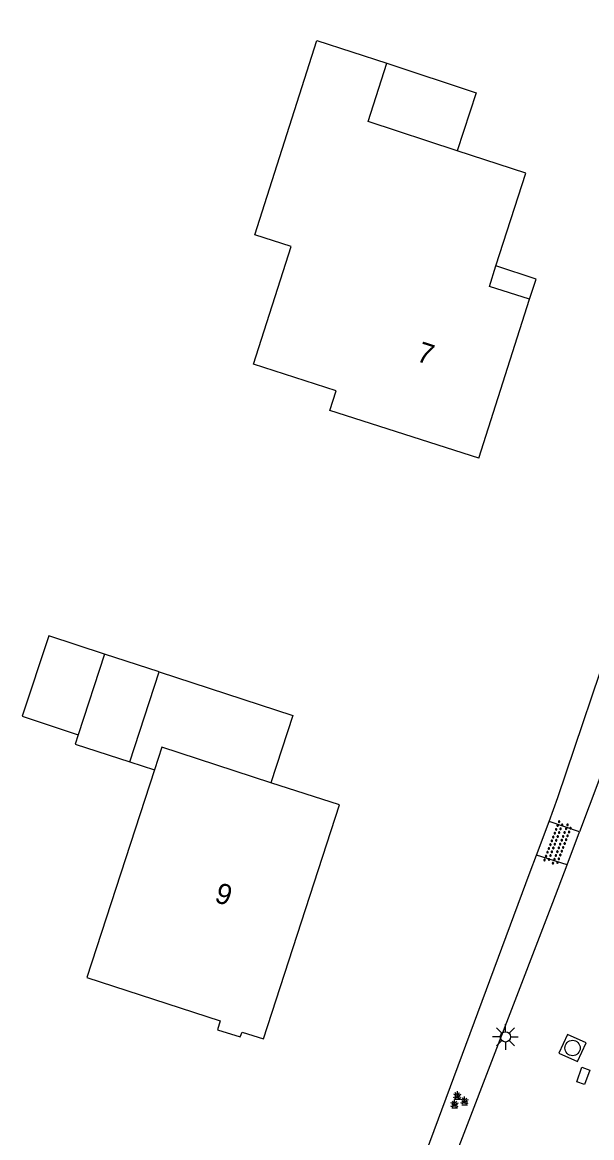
# Model space of a CAD drawing. Extents: x 128999 to 131010, y 395498 to 399007.
# Drawn here: x 130917.9 to 130945.7, y 396821 to 396875.4 of the extents above; entities that cross this region are included whole.
import ezdxf

# ---------------------------------------------------------------- set-up
doc = ezdxf.new("R2010")
doc.units = 0
for name, color, linetype in [('gg-afsc-erfafscheiding', 7, 'Continuous'), ('gg-anno-huisnummerreeks BGT', 7, 'Continuous'), ('gg-bbg-bijgebouw', 7, 'Continuous'), ('gg-bbg-gedigitaliseerde bebouwing', 7, 'Continuous'), ('gg-bbg-gedigitaliseerde bijgebouw', 7, 'Continuous'), ('gg-bbg-hoofdgebouw', 7, 'Continuous'), ('gg-bbg-luifel en loopbrug', 7, 'Continuous'), ('gg-knt-verharding', 7, 'Continuous'), ('gt-grn-groengrens', 7, 'Continuous'), ('gt-grn-weggrens', 7, 'Continuous'), ('gt-symb-groenvak', 7, 'Continuous'), ('gt-symb-kolk center center', 7, 'Continuous'), ('gt-symb-lichtmast', 7, 'Continuous'), ('gt-symb-overige verharding', 7, 'Continuous'), ('gt-symb-rioolschacht', 7, 'Continuous')]:
    doc.layers.add(name, color=color, linetype=linetype)

# ---------------------------------------------------------------- blocks, each defined once
blk = doc.blocks.new('gt0-KOLKCC')
at = {"layer": 'gt-symb-kolk center center'}
blk.add_lwpolyline([(-0.375, 0.2), (0.375, 0.2), (0.375, -0.2), (-0.375, -0.2)], close=True, dxfattribs=at)
blk = doc.blocks.new('gt0-GRVAK')
at = {"layer": 'gt-symb-groenvak'}
for p, q in [((-0.11, 0.189), (-0.228, 0.24)), ((-0.182, 0.153), (0.088, 0.153)), ((-0.091, 0.211), (-0.156, 0.322)), ((-0.047, 0.214), (-0.047, 0.393)), ((-0.004, 0.211), (0.061, 0.322)), ((0.015, 0.189), (0.133, 0.24)), ((0.262, -0.052), (0.197, 0.059)), ((0.305, -0.049), (0.305, 0.13)), ((0.349, -0.052), (0.414, 0.059)), ((-0.245, -0.228), (-0.363, -0.177)), ((-0.318, -0.264), (-0.047, -0.264)), ((-0.226, -0.206), (-0.291, -0.095)), ((-0.183, -0.203), (-0.183, -0.024)), ((-0.139, -0.206), (-0.074, -0.095)), ((-0.12, -0.228), (-0.002, -0.177)), ((0.243, -0.074), (0.125, -0.023)), ((0.17, -0.11), (0.441, -0.11)), ((0.368, -0.074), (0.486, -0.023))]:
    blk.add_line(p, q, dxfattribs=at)
blk = doc.blocks.new('gt0-LMAST')
at = {"layer": 'gt-symb-lichtmast'}
for p, q in [((-0.005, 0.246), (-0.005, 0.621)), ((-0.182, 0.173), (-0.447, 0.438)), ((0.172, 0.173), (0.437, 0.438)), ((-0.255, -0.004), (-0.63, -0.004)), ((-0.182, -0.181), (-0.447, -0.446)), ((-0.005, -0.254), (-0.005, -0.629)), ((0.437, -0.446), (0.172, -0.181)), ((0.245, -0.004), (0.62, -0.004))]:
    blk.add_line(p, q, dxfattribs=at)
blk.add_circle((-0.005, -0.004), 0.25, dxfattribs=at)
blk = doc.blocks.new('gt0-OVH')
at = {"layer": 'gt-symb-overige verharding'}
for points in [[(-0.972, 0.298), (-0.967, 0.308), (-0.965, 0.319), (-0.966, 0.33), (-0.971, 0.34), (-0.978, 0.348), (-0.988, 0.353), (-0.999, 0.355), (-1.01, 0.354), (-1.02, 0.349), (-1.028, 0.342), (-1.033, 0.332), (-1.035, 0.321), (-1.034, 0.31), (-1.029, 0.3), (-1.022, 0.292), (-1.012, 0.287), (-1.001, 0.285), (-0.99, 0.286), (-0.98, 0.291)], [(-0.872, 0.106), (-0.867, 0.116), (-0.865, 0.126), (-0.866, 0.137), (-0.871, 0.147), (-0.878, 0.156), (-0.888, 0.161), (-0.899, 0.163), (-0.91, 0.162), (-0.92, 0.157), (-0.928, 0.15), (-0.933, 0.14), (-0.935, 0.129), (-0.934, 0.118), (-0.929, 0.108), (-0.922, 0.1), (-0.912, 0.095), (-0.901, 0.092), (-0.89, 0.094), (-0.88, 0.098)], [(-0.772, 0.298), (-0.767, 0.308), (-0.765, 0.319), (-0.766, 0.33), (-0.771, 0.34), (-0.778, 0.348), (-0.788, 0.353), (-0.799, 0.355), (-0.81, 0.354), (-0.82, 0.349), (-0.828, 0.342), (-0.833, 0.332), (-0.835, 0.321), (-0.834, 0.31), (-0.829, 0.3), (-0.822, 0.292), (-0.812, 0.287), (-0.801, 0.285), (-0.79, 0.286), (-0.78, 0.291)], [(-0.672, 0.106), (-0.667, 0.116), (-0.665, 0.126), (-0.666, 0.137), (-0.671, 0.147), (-0.678, 0.156), (-0.688, 0.161), (-0.699, 0.163), (-0.71, 0.162), (-0.72, 0.157), (-0.728, 0.15), (-0.733, 0.14), (-0.735, 0.129), (-0.734, 0.118), (-0.729, 0.108), (-0.722, 0.1), (-0.712, 0.095), (-0.701, 0.092), (-0.69, 0.094), (-0.68, 0.098)], [(-0.572, 0.298), (-0.567, 0.308), (-0.565, 0.319), (-0.566, 0.33), (-0.571, 0.34), (-0.578, 0.348), (-0.588, 0.353), (-0.599, 0.355), (-0.61, 0.354), (-0.62, 0.349), (-0.628, 0.342), (-0.633, 0.332), (-0.635, 0.321), (-0.634, 0.31), (-0.629, 0.3), (-0.622, 0.292), (-0.612, 0.287), (-0.601, 0.285), (-0.59, 0.286), (-0.58, 0.291)], [(-0.472, 0.106), (-0.467, 0.116), (-0.465, 0.126), (-0.466, 0.137), (-0.471, 0.147), (-0.478, 0.156), (-0.488, 0.161), (-0.499, 0.163), (-0.51, 0.162), (-0.52, 0.157), (-0.528, 0.15), (-0.533, 0.14), (-0.535, 0.129), (-0.534, 0.118), (-0.529, 0.108), (-0.522, 0.1), (-0.512, 0.095), (-0.501, 0.092), (-0.49, 0.094), (-0.48, 0.098)], [(-0.372, 0.298), (-0.367, 0.308), (-0.365, 0.319), (-0.366, 0.33), (-0.371, 0.34), (-0.378, 0.348), (-0.388, 0.353), (-0.399, 0.355), (-0.41, 0.354), (-0.42, 0.349), (-0.428, 0.342), (-0.433, 0.332), (-0.435, 0.321), (-0.434, 0.31), (-0.429, 0.3), (-0.422, 0.292), (-0.412, 0.287), (-0.401, 0.285), (-0.39, 0.286), (-0.38, 0.291)], [(-0.272, 0.106), (-0.267, 0.116), (-0.265, 0.126), (-0.266, 0.137), (-0.271, 0.147), (-0.278, 0.156), (-0.288, 0.161), (-0.299, 0.163), (-0.31, 0.162), (-0.32, 0.157), (-0.328, 0.15), (-0.333, 0.14), (-0.335, 0.129), (-0.334, 0.118), (-0.329, 0.108), (-0.322, 0.1), (-0.312, 0.095), (-0.301, 0.092), (-0.29, 0.094), (-0.28, 0.098)], [(-0.172, 0.298), (-0.167, 0.308), (-0.165, 0.319), (-0.166, 0.33), (-0.171, 0.34), (-0.178, 0.348), (-0.188, 0.353), (-0.199, 0.355), (-0.21, 0.354), (-0.22, 0.349), (-0.228, 0.342), (-0.233, 0.332), (-0.235, 0.321), (-0.234, 0.31), (-0.229, 0.3), (-0.222, 0.292), (-0.212, 0.287), (-0.201, 0.285), (-0.19, 0.286), (-0.18, 0.291)], [(-0.072, 0.106), (-0.067, 0.116), (-0.065, 0.126), (-0.066, 0.137), (-0.071, 0.147), (-0.078, 0.156), (-0.088, 0.161), (-0.099, 0.163), (-0.11, 0.162), (-0.12, 0.157), (-0.128, 0.15), (-0.133, 0.14), (-0.135, 0.129), (-0.134, 0.118), (-0.129, 0.108), (-0.122, 0.1), (-0.112, 0.095), (-0.101, 0.092), (-0.09, 0.094), (-0.08, 0.098)], [(0.028, 0.298), (0.033, 0.308), (0.035, 0.319), (0.034, 0.33), (0.029, 0.34), (0.022, 0.348), (0.012, 0.353), (0.001, 0.355), (-0.01, 0.354), (-0.02, 0.349), (-0.028, 0.342), (-0.033, 0.332), (-0.035, 0.321), (-0.034, 0.31), (-0.029, 0.3), (-0.022, 0.292), (-0.012, 0.287), (-0.001, 0.285), (0.01, 0.286), (0.02, 0.291)], [(0.128, 0.106), (0.133, 0.116), (0.135, 0.126), (0.134, 0.137), (0.129, 0.147), (0.122, 0.156), (0.112, 0.161), (0.101, 0.163), (0.09, 0.162), (0.08, 0.157), (0.072, 0.15), (0.067, 0.14), (0.065, 0.129), (0.066, 0.118), (0.071, 0.108), (0.078, 0.1), (0.088, 0.095), (0.099, 0.092), (0.11, 0.094), (0.12, 0.098)], [(0.228, 0.298), (0.233, 0.308), (0.235, 0.319), (0.234, 0.33), (0.229, 0.34), (0.222, 0.348), (0.212, 0.353), (0.201, 0.355), (0.19, 0.354), (0.18, 0.349), (0.172, 0.342), (0.167, 0.332), (0.165, 0.321), (0.166, 0.31), (0.171, 0.3), (0.178, 0.292), (0.188, 0.287), (0.199, 0.285), (0.21, 0.286), (0.22, 0.291)], [(0.328, 0.106), (0.333, 0.116), (0.335, 0.126), (0.334, 0.137), (0.329, 0.147), (0.322, 0.156), (0.312, 0.161), (0.301, 0.163), (0.29, 0.162), (0.28, 0.157), (0.272, 0.15), (0.267, 0.14), (0.265, 0.129), (0.266, 0.118), (0.271, 0.108), (0.278, 0.1), (0.288, 0.095), (0.299, 0.092), (0.31, 0.094), (0.32, 0.098)], [(0.428, 0.298), (0.433, 0.308), (0.435, 0.319), (0.434, 0.33), (0.429, 0.34), (0.422, 0.348), (0.412, 0.353), (0.401, 0.355), (0.39, 0.354), (0.38, 0.349), (0.372, 0.342), (0.367, 0.332), (0.365, 0.321), (0.366, 0.31), (0.371, 0.3), (0.378, 0.292), (0.388, 0.287), (0.399, 0.285), (0.41, 0.286), (0.42, 0.291)], [(0.528, 0.106), (0.533, 0.116), (0.535, 0.126), (0.534, 0.137), (0.529, 0.147), (0.522, 0.156), (0.512, 0.161), (0.501, 0.163), (0.49, 0.162), (0.48, 0.157), (0.472, 0.15), (0.467, 0.14), (0.465, 0.129), (0.466, 0.118), (0.471, 0.108), (0.478, 0.1), (0.488, 0.095), (0.499, 0.092), (0.51, 0.094), (0.52, 0.098)], [(0.628, 0.298), (0.633, 0.308), (0.635, 0.319), (0.634, 0.33), (0.629, 0.34), (0.622, 0.348), (0.612, 0.353), (0.601, 0.355), (0.59, 0.354), (0.58, 0.349), (0.572, 0.342), (0.567, 0.332), (0.565, 0.321), (0.566, 0.31), (0.571, 0.3), (0.578, 0.292), (0.588, 0.287), (0.599, 0.285), (0.61, 0.286), (0.62, 0.291)], [(0.728, 0.106), (0.733, 0.116), (0.735, 0.126), (0.734, 0.137), (0.729, 0.147), (0.722, 0.156), (0.712, 0.161), (0.701, 0.163), (0.69, 0.162), (0.68, 0.157), (0.672, 0.15), (0.667, 0.14), (0.665, 0.129), (0.666, 0.118), (0.671, 0.108), (0.678, 0.1), (0.688, 0.095), (0.699, 0.092), (0.71, 0.094), (0.72, 0.098)], [(0.828, 0.298), (0.833, 0.308), (0.835, 0.319), (0.834, 0.33), (0.829, 0.34), (0.822, 0.348), (0.812, 0.353), (0.801, 0.355), (0.79, 0.354), (0.78, 0.349), (0.772, 0.342), (0.767, 0.332), (0.765, 0.321), (0.766, 0.31), (0.771, 0.3), (0.778, 0.292), (0.788, 0.287), (0.799, 0.285), (0.81, 0.286), (0.82, 0.291)], [(0.928, 0.106), (0.933, 0.116), (0.935, 0.126), (0.934, 0.137), (0.929, 0.147), (0.922, 0.156), (0.912, 0.161), (0.901, 0.163), (0.89, 0.162), (0.88, 0.157), (0.872, 0.15), (0.867, 0.14), (0.865, 0.129), (0.866, 0.118), (0.871, 0.108), (0.878, 0.1), (0.888, 0.095), (0.899, 0.092), (0.91, 0.094), (0.92, 0.098)], [(1.028, 0.298), (1.033, 0.308), (1.035, 0.319), (1.034, 0.33), (1.029, 0.34), (1.022, 0.348), (1.012, 0.353), (1.001, 0.355), (0.99, 0.354), (0.98, 0.349), (0.972, 0.342), (0.967, 0.332), (0.965, 0.321), (0.966, 0.31), (0.971, 0.3), (0.978, 0.292), (0.988, 0.287), (0.999, 0.285), (1.01, 0.286), (1.02, 0.291)], [(-0.972, -0.142), (-0.967, -0.132), (-0.965, -0.121), (-0.966, -0.11), (-0.971, -0.1), (-0.978, -0.092), (-0.988, -0.087), (-0.999, -0.085), (-1.01, -0.086), (-1.02, -0.091), (-1.028, -0.098), (-1.033, -0.108), (-1.035, -0.119), (-1.034, -0.13), (-1.029, -0.14), (-1.022, -0.148), (-1.012, -0.153), (-1.001, -0.155), (-0.99, -0.154), (-0.98, -0.149)], [(-0.872, -0.334), (-0.867, -0.324), (-0.865, -0.314), (-0.866, -0.303), (-0.871, -0.293), (-0.878, -0.284), (-0.888, -0.279), (-0.899, -0.277), (-0.91, -0.278), (-0.92, -0.283), (-0.928, -0.29), (-0.933, -0.3), (-0.935, -0.311), (-0.934, -0.322), (-0.929, -0.332), (-0.922, -0.34), (-0.912, -0.345), (-0.901, -0.348), (-0.89, -0.346), (-0.88, -0.342)], [(-0.772, -0.142), (-0.767, -0.132), (-0.765, -0.121), (-0.766, -0.11), (-0.771, -0.1), (-0.778, -0.092), (-0.788, -0.087), (-0.799, -0.085), (-0.81, -0.086), (-0.82, -0.091), (-0.828, -0.098), (-0.833, -0.108), (-0.835, -0.119), (-0.834, -0.13), (-0.829, -0.14), (-0.822, -0.148), (-0.812, -0.153), (-0.801, -0.155), (-0.79, -0.154), (-0.78, -0.149)], [(-0.672, -0.334), (-0.667, -0.324), (-0.665, -0.314), (-0.666, -0.303), (-0.671, -0.293), (-0.678, -0.284), (-0.688, -0.279), (-0.699, -0.277), (-0.71, -0.278), (-0.72, -0.283), (-0.728, -0.29), (-0.733, -0.3), (-0.735, -0.311), (-0.734, -0.322), (-0.729, -0.332), (-0.722, -0.34), (-0.712, -0.345), (-0.701, -0.348), (-0.69, -0.346), (-0.68, -0.342)], [(-0.572, -0.142), (-0.567, -0.132), (-0.565, -0.121), (-0.566, -0.11), (-0.571, -0.1), (-0.578, -0.092), (-0.588, -0.087), (-0.599, -0.085), (-0.61, -0.086), (-0.62, -0.091), (-0.628, -0.098), (-0.633, -0.108), (-0.635, -0.119), (-0.634, -0.13), (-0.629, -0.14), (-0.622, -0.148), (-0.612, -0.153), (-0.601, -0.155), (-0.59, -0.154), (-0.58, -0.149)], [(-0.472, -0.334), (-0.467, -0.324), (-0.465, -0.314), (-0.466, -0.303), (-0.471, -0.293), (-0.478, -0.284), (-0.488, -0.279), (-0.499, -0.277), (-0.51, -0.278), (-0.52, -0.283), (-0.528, -0.29), (-0.533, -0.3), (-0.535, -0.311), (-0.534, -0.322), (-0.529, -0.332), (-0.522, -0.34), (-0.512, -0.345), (-0.501, -0.348), (-0.49, -0.346), (-0.48, -0.342)], [(-0.372, -0.142), (-0.367, -0.132), (-0.365, -0.121), (-0.366, -0.11), (-0.371, -0.1), (-0.378, -0.092), (-0.388, -0.087), (-0.399, -0.085), (-0.41, -0.086), (-0.42, -0.091), (-0.428, -0.098), (-0.433, -0.108), (-0.435, -0.119), (-0.434, -0.13), (-0.429, -0.14), (-0.422, -0.148), (-0.412, -0.153), (-0.401, -0.155), (-0.39, -0.154), (-0.38, -0.149)], [(-0.272, -0.334), (-0.267, -0.324), (-0.265, -0.314), (-0.266, -0.303), (-0.271, -0.293), (-0.278, -0.284), (-0.288, -0.279), (-0.299, -0.277), (-0.31, -0.278), (-0.32, -0.283), (-0.328, -0.29), (-0.333, -0.3), (-0.335, -0.311), (-0.334, -0.322), (-0.329, -0.332), (-0.322, -0.34), (-0.312, -0.345), (-0.301, -0.348), (-0.29, -0.346), (-0.28, -0.342)], [(-0.172, -0.142), (-0.167, -0.132), (-0.165, -0.121), (-0.166, -0.11), (-0.171, -0.1), (-0.178, -0.092), (-0.188, -0.087), (-0.199, -0.085), (-0.21, -0.086), (-0.22, -0.091), (-0.228, -0.098), (-0.233, -0.108), (-0.235, -0.119), (-0.234, -0.13), (-0.229, -0.14), (-0.222, -0.148), (-0.212, -0.153), (-0.201, -0.155), (-0.19, -0.154), (-0.18, -0.149)], [(-0.072, -0.334), (-0.067, -0.324), (-0.065, -0.314), (-0.066, -0.303), (-0.071, -0.293), (-0.078, -0.284), (-0.088, -0.279), (-0.099, -0.277), (-0.11, -0.278), (-0.12, -0.283), (-0.128, -0.29), (-0.133, -0.3), (-0.135, -0.311), (-0.134, -0.322), (-0.129, -0.332), (-0.122, -0.34), (-0.112, -0.345), (-0.101, -0.348), (-0.09, -0.346), (-0.08, -0.342)], [(0.028, -0.142), (0.033, -0.132), (0.035, -0.121), (0.034, -0.11), (0.029, -0.1), (0.022, -0.092), (0.012, -0.087), (0.001, -0.085), (-0.01, -0.086), (-0.02, -0.091), (-0.028, -0.098), (-0.033, -0.108), (-0.035, -0.119), (-0.034, -0.13), (-0.029, -0.14), (-0.022, -0.148), (-0.012, -0.153), (-0.001, -0.155), (0.01, -0.154), (0.02, -0.149)], [(0.128, -0.334), (0.133, -0.324), (0.135, -0.314), (0.134, -0.303), (0.129, -0.293), (0.122, -0.284), (0.112, -0.279), (0.101, -0.277), (0.09, -0.278), (0.08, -0.283), (0.072, -0.29), (0.067, -0.3), (0.065, -0.311), (0.066, -0.322), (0.071, -0.332), (0.078, -0.34), (0.088, -0.345), (0.099, -0.348), (0.11, -0.346), (0.12, -0.342)], [(0.228, -0.142), (0.233, -0.132), (0.235, -0.121), (0.234, -0.11), (0.229, -0.1), (0.222, -0.092), (0.212, -0.087), (0.201, -0.085), (0.19, -0.086), (0.18, -0.091), (0.172, -0.098), (0.167, -0.108), (0.165, -0.119), (0.166, -0.13), (0.171, -0.14), (0.178, -0.148), (0.188, -0.153), (0.199, -0.155), (0.21, -0.154), (0.22, -0.149)], [(0.328, -0.334), (0.333, -0.324), (0.335, -0.314), (0.334, -0.303), (0.329, -0.293), (0.322, -0.284), (0.312, -0.279), (0.301, -0.277), (0.29, -0.278), (0.28, -0.283), (0.272, -0.29), (0.267, -0.3), (0.265, -0.311), (0.266, -0.322), (0.271, -0.332), (0.278, -0.34), (0.288, -0.345), (0.299, -0.348), (0.31, -0.346), (0.32, -0.342)], [(0.428, -0.142), (0.433, -0.132), (0.435, -0.121), (0.434, -0.11), (0.429, -0.1), (0.422, -0.092), (0.412, -0.087), (0.401, -0.085), (0.39, -0.086), (0.38, -0.091), (0.372, -0.098), (0.367, -0.108), (0.365, -0.119), (0.366, -0.13), (0.371, -0.14), (0.378, -0.148), (0.388, -0.153), (0.399, -0.155), (0.41, -0.154), (0.42, -0.149)], [(0.528, -0.334), (0.533, -0.324), (0.535, -0.314), (0.534, -0.303), (0.529, -0.293), (0.522, -0.284), (0.512, -0.279), (0.501, -0.277), (0.49, -0.278), (0.48, -0.283), (0.472, -0.29), (0.467, -0.3), (0.465, -0.311), (0.466, -0.322), (0.471, -0.332), (0.478, -0.34), (0.488, -0.345), (0.499, -0.348), (0.51, -0.346), (0.52, -0.342)], [(0.628, -0.142), (0.633, -0.132), (0.635, -0.121), (0.634, -0.11), (0.629, -0.1), (0.622, -0.092), (0.612, -0.087), (0.601, -0.085), (0.59, -0.086), (0.58, -0.091), (0.572, -0.098), (0.567, -0.108), (0.565, -0.119), (0.566, -0.13), (0.571, -0.14), (0.578, -0.148), (0.588, -0.153), (0.599, -0.155), (0.61, -0.154), (0.62, -0.149)], [(0.728, -0.334), (0.733, -0.324), (0.735, -0.314), (0.734, -0.303), (0.729, -0.293), (0.722, -0.284), (0.712, -0.279), (0.701, -0.277), (0.69, -0.278), (0.68, -0.283), (0.672, -0.29), (0.667, -0.3), (0.665, -0.311), (0.666, -0.322), (0.671, -0.332), (0.678, -0.34), (0.688, -0.345), (0.699, -0.348), (0.71, -0.346), (0.72, -0.342)], [(0.828, -0.142), (0.833, -0.132), (0.835, -0.121), (0.834, -0.11), (0.829, -0.1), (0.822, -0.092), (0.812, -0.087), (0.801, -0.085), (0.79, -0.086), (0.78, -0.091), (0.772, -0.098), (0.767, -0.108), (0.765, -0.119), (0.766, -0.13), (0.771, -0.14), (0.778, -0.148), (0.788, -0.153), (0.799, -0.155), (0.81, -0.154), (0.82, -0.149)], [(0.928, -0.334), (0.933, -0.324), (0.935, -0.314), (0.934, -0.303), (0.929, -0.293), (0.922, -0.284), (0.912, -0.279), (0.901, -0.277), (0.89, -0.278), (0.88, -0.283), (0.872, -0.29), (0.867, -0.3), (0.865, -0.311), (0.866, -0.322), (0.871, -0.332), (0.878, -0.34), (0.888, -0.345), (0.899, -0.348), (0.91, -0.346), (0.92, -0.342)], [(1.028, -0.142), (1.033, -0.132), (1.035, -0.121), (1.034, -0.11), (1.029, -0.1), (1.022, -0.092), (1.012, -0.087), (1.001, -0.085), (0.99, -0.086), (0.98, -0.091), (0.972, -0.098), (0.967, -0.108), (0.965, -0.119), (0.966, -0.13), (0.971, -0.14), (0.978, -0.148), (0.988, -0.153), (0.999, -0.155), (1.01, -0.154), (1.02, -0.149)]]:
    blk.add_lwpolyline(points, close=True, dxfattribs=at)
blk = doc.blocks.new('gt0-RS')
at = {"layer": 'gt-symb-rioolschacht'}
blk.add_lwpolyline([(-0.5, -0.5), (0.5, -0.5), (0.5, 0.5), (-0.5, 0.5)], close=True, dxfattribs=at)
blk.add_circle((0, 0), 0.375, dxfattribs=at)

msp = doc.modelspace()

# ---------------------------------------------------------------- linework, layer by layer
at = {"layer": 'gg-afsc-erfafscheiding'}
for p, q in [((130944.074, 396837.561), (130953.179, 396864.648)), ((130935.347, 396814.064), (130942.723, 396833.94))]:
    msp.add_line(p, q, dxfattribs=at)
at = {"layer": 'gg-bbg-bijgebouw'}
msp.add_line((130923.195, 396839.306), (130924.622, 396843.704), dxfattribs=at)
at = {"layer": 'gg-bbg-gedigitaliseerde bebouwing'}
msp.add_line((130924.745, 396840.017), (130924.388, 396838.918), dxfattribs=at)
for points in [[(130940.21, 396854.13), (130932.946, 396856.447), (130933.256, 396857.419), (130929.22, 396858.711), (130931.059, 396864.458), (130929.284, 396865.026), (130932.319, 396874.51), (130935.72, 396873.4)], [(130924.388, 396838.918), (130921.096, 396828.776), (130927.601, 396826.665), (130927.46, 396826.23)]]:
    msp.add_lwpolyline(points, dxfattribs=at)
at = {"layer": 'gg-bbg-gedigitaliseerde bijgebouw'}
for p, q in [((130921.954, 396844.57), (130920.676, 396840.632)), ((130924.622, 396843.704), (130921.954, 396844.57))]:
    msp.add_line(p, q, dxfattribs=at)
msp.add_lwpolyline([(130920.676, 396840.632), (130920.527, 396840.172), (130923.195, 396839.306)], dxfattribs=at)
at = {"layer": 'gg-bbg-hoofdgebouw'}
for p, q in [((130940.21, 396854.13), (130942.69, 396861.88)), ((130930.061, 396838.291), (130924.745, 396840.017))]:
    msp.add_line(p, q, dxfattribs=at)
for points in [[(130939.16, 396869.132), (130934.82, 396870.56), (130935.72, 396873.4)], [(130941.052, 396863.507), (130942.51, 396868.03), (130939.16, 396869.132)], [(130942.69, 396861.88), (130940.73, 396862.51), (130941.052, 396863.507)], [(130927.46, 396826.23), (130928.58, 396825.88), (130928.67, 396826.12), (130929.71, 396825.79), (130933.414, 396837.202), (130930.061, 396838.291)]]:
    msp.add_lwpolyline(points, dxfattribs=at)
at = {"layer": 'gg-bbg-luifel en loopbrug'}
msp.add_line((130923.195, 396839.306), (130924.388, 396838.918), dxfattribs=at)
for points in [[(130935.72, 396873.4), (130940.091, 396871.962), (130939.16, 396869.132)], [(130942.69, 396861.88), (130943.013, 396862.862), (130941.052, 396863.507)], [(130921.954, 396844.57), (130919.239, 396845.463), (130917.945, 396841.531), (130920.676, 396840.632)], [(130924.622, 396843.704), (130931.136, 396841.561), (130930.061, 396838.291)]]:
    msp.add_lwpolyline(points, dxfattribs=at)
at = {"layer": 'gg-knt-verharding'}
for p, q in [((130945.122, 396835.893), (130943.641, 396836.401)), ((130944.518, 396834.287), (130945.122, 396835.893)), ((130944.518, 396834.287), (130943.026, 396834.753))]:
    msp.add_line(p, q, dxfattribs=at)
for points in [[(130963.617, 396892.719), (130960.95, 396883.919), (130957.476, 396872.165), (130954.992, 396864.034), (130949.508, 396847.557), (130945.122, 396835.893)], [(130936.598, 396813.647), (130943.822, 396832.436), (130944.518, 396834.287)]]:
    msp.add_lwpolyline(points, dxfattribs=at)
at = {"layer": 'gt-grn-groengrens'}
for p, q in [((130943.641, 396836.401), (130944.074, 396837.561)), ((130942.723, 396833.94), (130943.026, 396834.753))]:
    msp.add_line(p, q, dxfattribs=at)
at = {"layer": 'gt-grn-weggrens'}
msp.add_line((130943.026, 396834.753), (130943.641, 396836.401), dxfattribs=at)

# ---------------------------------------------------------------- block references
at = {"layer": 'gt-symb-groenvak'}
for p in [(130939.215, 396822.686), (130939.218, 396822.849)]:
    msp.add_blockref('gt0-GRVAK', p, dxfattribs=at)
at = {"layer": 'gt-symb-kolk center center', "rotation": 70.2421000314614}
msp.add_blockref('gt0-KOLKCC', (130945.309, 396823.983), dxfattribs=at)
at = {"layer": 'gt-symb-lichtmast'}
msp.add_blockref('gt0-LMAST', (130941.516, 396825.886), dxfattribs=at)
at = {"layer": 'gt-symb-overige verharding', "rotation": 69.2092747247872}
msp.add_blockref('gt0-OVH', (130944.075, 396835.339), dxfattribs=at)
at = {"layer": 'gt-symb-rioolschacht', "rotation": 65.22886109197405}
msp.add_blockref('gt0-RS', (130944.787, 396825.342), dxfattribs=at)

# ---------------------------------------------------------------- texts
at = {"layer": 'gg-anno-huisnummerreeks BGT'}
for s, rotation, p in [('7', 342.2, (130937.123, 396858.885)), ('9', 342, (130927.271, 396832.491))]:
    msp.add_text(s, height=1, rotation=rotation, dxfattribs=at).set_placement(p)

doc.saveas('drawing.dxf')
